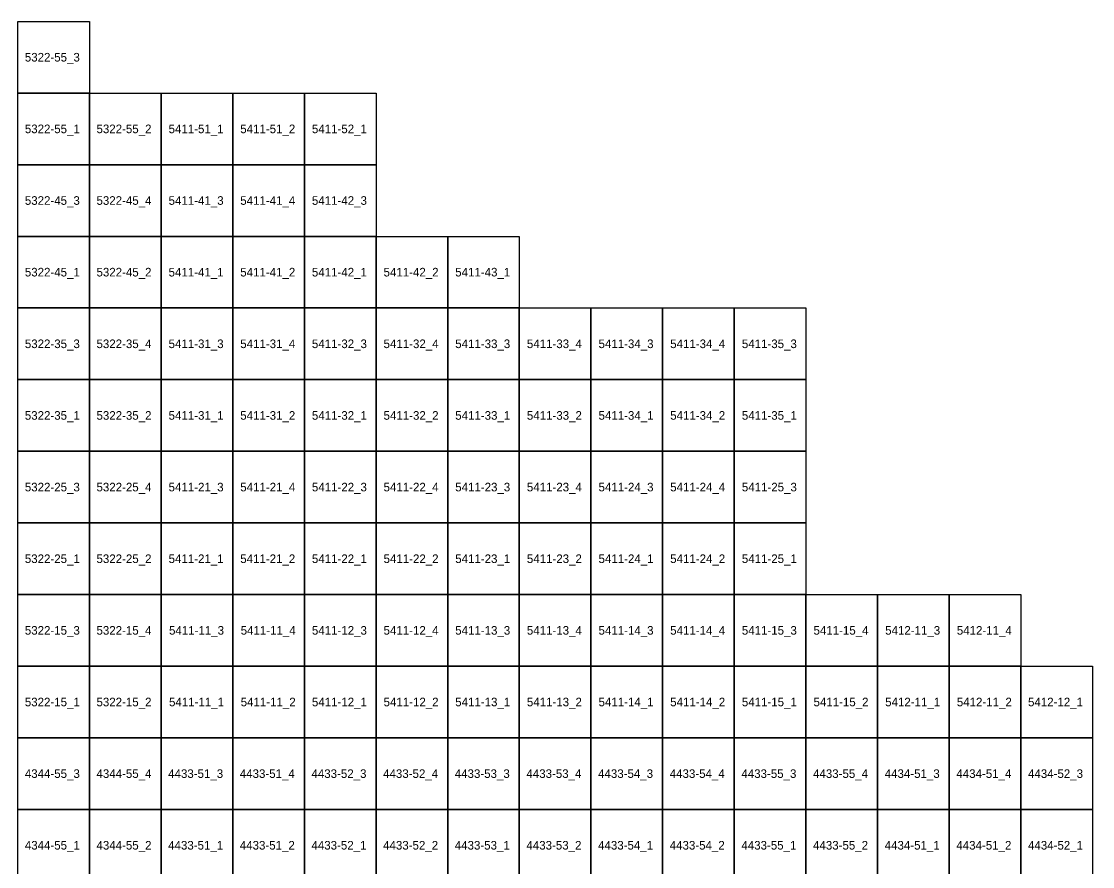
# Model space of a CAD drawing. Extents: x 312500 to 765000, y 172500 to 440000.
# Drawn here: x 595129 to 632500, y 395507 to 425000 of the extents above; entities that cross this region are included whole.
import ezdxf

# ---------------------------------------------------------------- set-up
doc = ezdxf.new("R2010")
doc.units = 0
doc.layers.add('Topo5_ramis_TKS2025', color=7, linetype='Continuous')
doc.layers.add('Topo5_ramis_TKS2025_Nr', color=7, linetype='Continuous')

msp = doc.modelspace()

# ---------------------------------------------------------------- linework, layer by layer
at = {"layer": 'Topo5_ramis_TKS2025'}
for points in [[(595000, 422500), (595000, 425000), (597500, 425000), (597500, 422500), (595000, 422500)], [(595000, 420000), (595000, 422500), (597500, 422500), (597500, 420000), (595000, 420000)], [(597500, 420000), (597500, 422500), (600000, 422500), (600000, 420000), (597500, 420000)], [(600000, 420000), (600000, 422500), (602500, 422500), (602500, 420000), (600000, 420000)], [(602500, 420000), (602500, 422500), (605000, 422500), (605000, 420000), (602500, 420000)], [(605000, 420000), (605000, 422500), (607500, 422500), (607500, 420000), (605000, 420000)], [(595000, 417500), (595000, 420000), (597500, 420000), (597500, 417500), (595000, 417500)], [(597500, 417500), (597500, 420000), (600000, 420000), (600000, 417500), (597500, 417500)], [(600000, 417500), (600000, 420000), (602500, 420000), (602500, 417500), (600000, 417500)], [(602500, 417500), (602500, 420000), (605000, 420000), (605000, 417500), (602500, 417500)], [(605000, 417500), (605000, 420000), (607500, 420000), (607500, 417500), (605000, 417500)], [(595000, 415000), (595000, 417500), (597500, 417500), (597500, 415000), (595000, 415000)], [(597500, 415000), (597500, 417500), (600000, 417500), (600000, 415000), (597500, 415000)], [(600000, 415000), (600000, 417500), (602500, 417500), (602500, 415000), (600000, 415000)], [(602500, 415000), (602500, 417500), (605000, 417500), (605000, 415000), (602500, 415000)], [(605000, 415000), (605000, 417500), (607500, 417500), (607500, 415000), (605000, 415000)], [(607500, 415000), (607500, 417500), (610000, 417500), (610000, 415000), (607500, 415000)], [(610000, 415000), (610000, 417500), (612500, 417500), (612500, 415000), (610000, 415000)], [(595000, 412500), (595000, 415000), (597500, 415000), (597500, 412500), (595000, 412500)], [(597500, 412500), (597500, 415000), (600000, 415000), (600000, 412500), (597500, 412500)], [(600000, 412500), (600000, 415000), (602500, 415000), (602500, 412500), (600000, 412500)], [(602500, 412500), (602500, 415000), (605000, 415000), (605000, 412500), (602500, 412500)], [(605000, 412500), (605000, 415000), (607500, 415000), (607500, 412500), (605000, 412500)], [(607500, 412500), (607500, 415000), (610000, 415000), (610000, 412500), (607500, 412500)], [(610000, 412500), (610000, 415000), (612500, 415000), (612500, 412500), (610000, 412500)], [(612500, 412500), (612500, 415000), (615000, 415000), (615000, 412500), (612500, 412500)], [(615000, 412500), (615000, 415000), (617500, 415000), (617500, 412500), (615000, 412500)], [(617500, 412500), (617500, 415000), (620000, 415000), (620000, 412500), (617500, 412500)], [(620000, 412500), (620000, 415000), (622500, 415000), (622500, 412500), (620000, 412500)], [(595000, 410000), (595000, 412500), (597500, 412500), (597500, 410000), (595000, 410000)], [(597500, 410000), (597500, 412500), (600000, 412500), (600000, 410000), (597500, 410000)], [(600000, 410000), (600000, 412500), (602500, 412500), (602500, 410000), (600000, 410000)], [(602500, 410000), (602500, 412500), (605000, 412500), (605000, 410000), (602500, 410000)], [(605000, 410000), (605000, 412500), (607500, 412500), (607500, 410000), (605000, 410000)], [(607500, 410000), (607500, 412500), (610000, 412500), (610000, 410000), (607500, 410000)], [(610000, 410000), (610000, 412500), (612500, 412500), (612500, 410000), (610000, 410000)], [(612500, 410000), (612500, 412500), (615000, 412500), (615000, 410000), (612500, 410000)], [(615000, 410000), (615000, 412500), (617500, 412500), (617500, 410000), (615000, 410000)], [(617500, 410000), (617500, 412500), (620000, 412500), (620000, 410000), (617500, 410000)], [(620000, 410000), (620000, 412500), (622500, 412500), (622500, 410000), (620000, 410000)], [(595000, 407500), (595000, 410000), (597500, 410000), (597500, 407500), (595000, 407500)], [(597500, 407500), (597500, 410000), (600000, 410000), (600000, 407500), (597500, 407500)], [(600000, 407500), (600000, 410000), (602500, 410000), (602500, 407500), (600000, 407500)], [(602500, 407500), (602500, 410000), (605000, 410000), (605000, 407500), (602500, 407500)], [(605000, 407500), (605000, 410000), (607500, 410000), (607500, 407500), (605000, 407500)], [(607500, 407500), (607500, 410000), (610000, 410000), (610000, 407500), (607500, 407500)], [(610000, 407500), (610000, 410000), (612500, 410000), (612500, 407500), (610000, 407500)], [(612500, 407500), (612500, 410000), (615000, 410000), (615000, 407500), (612500, 407500)], [(615000, 407500), (615000, 410000), (617500, 410000), (617500, 407500), (615000, 407500)], [(617500, 407500), (617500, 410000), (620000, 410000), (620000, 407500), (617500, 407500)], [(620000, 407500), (620000, 410000), (622500, 410000), (622500, 407500), (620000, 407500)], [(595000, 405000), (595000, 407500), (597500, 407500), (597500, 405000), (595000, 405000)], [(597500, 405000), (597500, 407500), (600000, 407500), (600000, 405000), (597500, 405000)], [(600000, 405000), (600000, 407500), (602500, 407500), (602500, 405000), (600000, 405000)], [(602500, 405000), (602500, 407500), (605000, 407500), (605000, 405000), (602500, 405000)], [(605000, 405000), (605000, 407500), (607500, 407500), (607500, 405000), (605000, 405000)], [(607500, 405000), (607500, 407500), (610000, 407500), (610000, 405000), (607500, 405000)], [(610000, 405000), (610000, 407500), (612500, 407500), (612500, 405000), (610000, 405000)], [(612500, 405000), (612500, 407500), (615000, 407500), (615000, 405000), (612500, 405000)], [(615000, 405000), (615000, 407500), (617500, 407500), (617500, 405000), (615000, 405000)], [(617500, 405000), (617500, 407500), (620000, 407500), (620000, 405000), (617500, 405000)], [(620000, 405000), (620000, 407500), (622500, 407500), (622500, 405000), (620000, 405000)], [(595000, 402500), (595000, 405000), (597500, 405000), (597500, 402500), (595000, 402500)], [(597500, 402500), (597500, 405000), (600000, 405000), (600000, 402500), (597500, 402500)], [(600000, 402500), (600000, 405000), (602500, 405000), (602500, 402500), (600000, 402500)], [(602500, 402500), (602500, 405000), (605000, 405000), (605000, 402500), (602500, 402500)], [(605000, 402500), (605000, 405000), (607500, 405000), (607500, 402500), (605000, 402500)], [(607500, 402500), (607500, 405000), (610000, 405000), (610000, 402500), (607500, 402500)], [(610000, 402500), (610000, 405000), (612500, 405000), (612500, 402500), (610000, 402500)], [(612500, 402500), (612500, 405000), (615000, 405000), (615000, 402500), (612500, 402500)], [(615000, 402500), (615000, 405000), (617500, 405000), (617500, 402500), (615000, 402500)], [(617500, 402500), (617500, 405000), (620000, 405000), (620000, 402500), (617500, 402500)], [(620000, 402500), (620000, 405000), (622500, 405000), (622500, 402500), (620000, 402500)], [(622500, 402500), (622500, 405000), (625000, 405000), (625000, 402500), (622500, 402500)], [(625000, 402500), (625000, 405000), (627500, 405000), (627500, 402500), (625000, 402500)], [(627500, 402500), (627500, 405000), (630000, 405000), (630000, 402500), (627500, 402500)], [(595000, 400000), (595000, 402500), (597500, 402500), (597500, 400000), (595000, 400000)], [(597500, 400000), (597500, 402500), (600000, 402500), (600000, 400000), (597500, 400000)], [(600000, 400000), (600000, 402500), (602500, 402500), (602500, 400000), (600000, 400000)], [(602500, 400000), (602500, 402500), (605000, 402500), (605000, 400000), (602500, 400000)], [(605000, 400000), (605000, 402500), (607500, 402500), (607500, 400000), (605000, 400000)], [(607500, 400000), (607500, 402500), (610000, 402500), (610000, 400000), (607500, 400000)], [(610000, 400000), (610000, 402500), (612500, 402500), (612500, 400000), (610000, 400000)], [(612500, 400000), (612500, 402500), (615000, 402500), (615000, 400000), (612500, 400000)], [(615000, 400000), (615000, 402500), (617500, 402500), (617500, 400000), (615000, 400000)], [(617500, 400000), (617500, 402500), (620000, 402500), (620000, 400000), (617500, 400000)], [(620000, 400000), (620000, 402500), (622500, 402500), (622500, 400000), (620000, 400000)], [(622500, 400000), (622500, 402500), (625000, 402500), (625000, 400000), (622500, 400000)], [(625000, 400000), (625000, 402500), (627500, 402500), (627500, 400000), (625000, 400000)], [(627500, 400000), (627500, 402500), (630000, 402500), (630000, 400000), (627500, 400000)], [(630000, 400000), (630000, 402500), (632500, 402500), (632500, 400000), (630000, 400000)], [(595000, 397500), (595000, 400000), (597500, 400000), (597500, 397500), (595000, 397500)], [(597500, 397500), (597500, 400000), (600000, 400000), (600000, 397500), (597500, 397500)], [(600000, 397500), (600000, 400000), (602500, 400000), (602500, 397500), (600000, 397500)], [(602500, 397500), (602500, 400000), (605000, 400000), (605000, 397500), (602500, 397500)], [(605000, 397500), (605000, 400000), (607500, 400000), (607500, 397500), (605000, 397500)], [(607500, 397500), (607500, 400000), (610000, 400000), (610000, 397500), (607500, 397500)], [(610000, 397500), (610000, 400000), (612500, 400000), (612500, 397500), (610000, 397500)], [(612500, 397500), (612500, 400000), (615000, 400000), (615000, 397500), (612500, 397500)], [(615000, 397500), (615000, 400000), (617500, 400000), (617500, 397500), (615000, 397500)], [(617500, 397500), (617500, 400000), (620000, 400000), (620000, 397500), (617500, 397500)], [(620000, 397500), (620000, 400000), (622500, 400000), (622500, 397500), (620000, 397500)], [(622500, 397500), (622500, 400000), (625000, 400000), (625000, 397500), (622500, 397500)], [(625000, 397500), (625000, 400000), (627500, 400000), (627500, 397500), (625000, 397500)], [(627500, 397500), (627500, 400000), (630000, 400000), (630000, 397500), (627500, 397500)], [(630000, 397500), (630000, 400000), (632500, 400000), (632500, 397500), (630000, 397500)], [(595000, 395000), (595000, 397500), (597500, 397500), (597500, 395000), (595000, 395000)], [(597500, 395000), (597500, 397500), (600000, 397500), (600000, 395000), (597500, 395000)], [(600000, 395000), (600000, 397500), (602500, 397500), (602500, 395000), (600000, 395000)], [(602500, 395000), (602500, 397500), (605000, 397500), (605000, 395000), (602500, 395000)], [(605000, 395000), (605000, 397500), (607500, 397500), (607500, 395000), (605000, 395000)], [(607500, 395000), (607500, 397500), (610000, 397500), (610000, 395000), (607500, 395000)], [(610000, 395000), (610000, 397500), (612500, 397500), (612500, 395000), (610000, 395000)], [(612500, 395000), (612500, 397500), (615000, 397500), (615000, 395000), (612500, 395000)], [(615000, 395000), (615000, 397500), (617500, 397500), (617500, 395000), (615000, 395000)], [(617500, 395000), (617500, 397500), (620000, 397500), (620000, 395000), (617500, 395000)], [(620000, 395000), (620000, 397500), (622500, 397500), (622500, 395000), (620000, 395000)], [(622500, 395000), (622500, 397500), (625000, 397500), (625000, 395000), (622500, 395000)], [(625000, 395000), (625000, 397500), (627500, 397500), (627500, 395000), (625000, 395000)], [(627500, 395000), (627500, 397500), (630000, 397500), (630000, 395000), (627500, 395000)], [(630000, 395000), (630000, 397500), (632500, 397500), (632500, 395000), (630000, 395000)]]:
    msp.add_lwpolyline(points, dxfattribs=at)

# ---------------------------------------------------------------- texts
at = {"layer": 'Topo5_ramis_TKS2025_Nr'}
for s, p in [('5322-55_3', (595248, 423600)), ('5322-55_1', (595248, 421100)), ('5322-55_2', (597748, 421100)), ('5411-51_1', (600264, 421100)), ('5411-51_2', (602764, 421100)), ('5411-52_1', (605264, 421100)), ('5322-45_3', (595248, 418600)), ('5322-45_4', (597748, 418600)), ('5411-41_3', (600264, 418600)), ('5411-41_4', (602764, 418600)), ('5411-42_3', (605264, 418600)), ('5322-45_1', (595248, 416100)), ('5322-45_2', (597748, 416100)), ('5411-41_1', (600264, 416100)), ('5411-41_2', (602764, 416100)), ('5411-42_1', (605264, 416100)), ('5411-42_2', (607764, 416100)), ('5411-43_1', (610264, 416100)), ('5322-35_3', (595248, 413600)), ('5322-35_4', (597748, 413600)), ('5411-31_3', (600264, 413600)), ('5411-31_4', (602764, 413600)), ('5411-32_3', (605264, 413600)), ('5411-32_4', (607764, 413600)), ('5411-33_3', (610264, 413600)), ('5411-33_4', (612764, 413600)), ('5411-34_3', (615264, 413600)), ('5411-34_4', (617764, 413600)), ('5411-35_3', (620264, 413600)), ('5322-35_1', (595248, 411100)), ('5322-35_2', (597748, 411100)), ('5411-31_1', (600264, 411100)), ('5411-31_2', (602764, 411100)), ('5411-32_1', (605264, 411100)), ('5411-32_2', (607764, 411100)), ('5411-33_1', (610264, 411100)), ('5411-33_2', (612764, 411100)), ('5411-34_1', (615264, 411100)), ('5411-34_2', (617764, 411100)), ('5411-35_1', (620264, 411100)), ('5322-25_3', (595248, 408600)), ('5322-25_4', (597748, 408600)), ('5411-21_3', (600264, 408600)), ('5411-21_4', (602764, 408600)), ('5411-22_3', (605264, 408600)), ('5411-22_4', (607764, 408600)), ('5411-23_3', (610264, 408600)), ('5411-23_4', (612764, 408600)), ('5411-24_3', (615264, 408600)), ('5411-24_4', (617764, 408600)), ('5411-25_3', (620264, 408600)), ('5322-25_1', (595248, 406100)), ('5322-25_2', (597748, 406100)), ('5411-21_1', (600264, 406100)), ('5411-21_2', (602764, 406100)), ('5411-22_1', (605264, 406100)), ('5411-22_2', (607764, 406100)), ('5411-23_1', (610264, 406100)), ('5411-23_2', (612764, 406100)), ('5411-24_1', (615264, 406100)), ('5411-24_2', (617764, 406100)), ('5411-25_1', (620264, 406100)), ('5322-15_3', (595248, 403600)), ('5322-15_4', (597748, 403600)), ('5411-11_3', (600279, 403600)), ('5411-11_4', (602779, 403600)), ('5411-12_3', (605264, 403600)), ('5411-12_4', (607764, 403600)), ('5411-13_3', (610264, 403600)), ('5411-13_4', (612764, 403600)), ('5411-14_3', (615264, 403600)), ('5411-14_4', (617764, 403600)), ('5411-15_3', (620264, 403600)), ('5411-15_4', (622764, 403600)), ('5412-11_3', (625264, 403600)), ('5412-11_4', (627764, 403600)), ('5322-15_1', (595248, 401100)), ('5322-15_2', (597748, 401100)), ('5411-11_1', (600279, 401100)), ('5411-11_2', (602779, 401100)), ('5411-12_1', (605264, 401100)), ('5411-12_2', (607764, 401100)), ('5411-13_1', (610264, 401100)), ('5411-13_2', (612764, 401100)), ('5411-14_1', (615264, 401100)), ('5411-14_2', (617764, 401100)), ('5411-15_1', (620264, 401100)), ('5411-15_2', (622764, 401100)), ('5412-11_1', (625264, 401100)), ('5412-11_2', (627764, 401100)), ('5412-12_1', (630248, 401100)), ('4344-55_3', (595248, 398600)), ('4344-55_4', (597748, 398600)), ('4433-51_3', (600248, 398600)), ('4433-51_4', (602748, 398600)), ('4433-52_3', (605248, 398600)), ('4433-52_4', (607748, 398600)), ('4433-53_3', (610248, 398600)), ('4433-53_4', (612748, 398600)), ('4433-54_3', (615248, 398600)), ('4433-54_4', (617748, 398600)), ('4433-55_3', (620248, 398600)), ('4433-55_4', (622748, 398600)), ('4434-51_3', (625248, 398600)), ('4434-51_4', (627748, 398600)), ('4434-52_3', (630248, 398600)), ('4344-55_1', (595248, 396100)), ('4344-55_2', (597748, 396100)), ('4433-51_1', (600248, 396100)), ('4433-51_2', (602748, 396100)), ('4433-52_1', (605248, 396100)), ('4433-52_2', (607748, 396100)), ('4433-53_1', (610248, 396100)), ('4433-53_2', (612748, 396100)), ('4433-54_1', (615248, 396100)), ('4433-54_2', (617748, 396100)), ('4433-55_1', (620248, 396100)), ('4433-55_2', (622748, 396100)), ('4434-51_1', (625248, 396100)), ('4434-51_2', (627748, 396100)), ('4434-52_1', (630248, 396100))]:
    msp.add_text(s, height=300, dxfattribs=at).set_placement(p)

doc.saveas('drawing.dxf')
